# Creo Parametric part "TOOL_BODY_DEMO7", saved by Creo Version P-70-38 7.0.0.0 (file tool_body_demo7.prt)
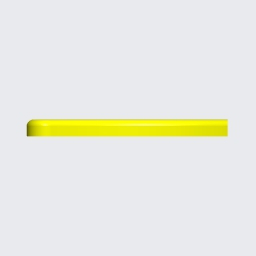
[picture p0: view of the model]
Units: millimeter Kilogram Sec (mmKs); MM, KILOGRAM, SECS
Materials in the file: NO_MATERIAL

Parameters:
  TITLE = "TITLE PARAMETER"
  DESCRIPTION = "DESCRIPTION PARAMETER"
  PART_NUMBER = "PARAMETER"
  DRAWN_BY = "PARAMETER"
  PROI_CREATED_BY = "nswadmin"
  PROI_CREATED_ON = "7/20/2004 11:43:31 AM"
  PROI_LOCATION = "Root Folder/Standards/Start Parts"
  AGILE_ITEM_NUMBER = "N/A"
  PTC_WM_ITERATION = "0"
  PTC_WM_VERSION = ".0"
  PTC_WM_CREATED_ON = "28-Aug-19 11:57:51 AM"
  PTC_WM_MODIFIED_ON = "28-Aug-19 11:57:51 AM"
  CATALOG_NUMBER = "XX####"

Created from: IN_ABSOLUTE_ACCURACY_MITG-BLDR.PRT

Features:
  1. datum plane "SIDE"
  2. datum plane "TOP"
  3. datum plane "FRONT"
  4. coordinate system
  5. extrusion "Extrude 1"
  6. round "Round 1"
  7. round "Round 3"
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
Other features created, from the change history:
  extruded cut "Extrude 2"
  round "Round 2"
  shell "Shell 1" (2 times)
  extruded cut "Extrude 3"
  extrusion "Extrude 4"
  chamfer "Chamfer 1"
  feature "Copy Geometry id 3942"
  extruded cut "Extrude 24"
  group "LOCAL_GROUP_20"
  feature "Body Subtract 1"

Other named items: CS0, BACK_ALL, BOTTOM_ALL, FRONT_ALL, LEFT_ALL, RIGHT_ALL, TOP_ALL, ANNOT_LAYER_STATE0001, ANNOT_LAYER_STATE0002, ANNOT_LAYER_STATE0003, ANNOT_LAYER_STATE0004, ANNOT_LAYER_STATE0005, ANNOT_LAYER_STATE0006

Layers: AXES, COPY_GEOMETRY, COSMETICS, DATUM_CSYS, DATUM_CURVES, DATUM_PLANES, DATUM_POINTS, SURFACES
